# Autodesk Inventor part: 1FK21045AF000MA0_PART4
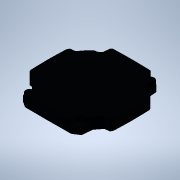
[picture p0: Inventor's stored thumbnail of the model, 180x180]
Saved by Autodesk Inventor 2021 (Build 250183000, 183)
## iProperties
Created: 2025-04
Part Number: 1FK21045AF000MA0_PART4
Material: Generic
Catalog Web Link: www.3dfindit.com
Description: -Servo synchronous motor
Document SubType Name: Modeling
Designer: psAdmin
Mass: 55.5405 g
Surface Area: 149.572 cm^2
Volume: 55.5405 cm^3
Density: 1 g/cm^3
Appearance: PSOLRGB-38-46-56
Category: PARTsolutions
Title: 1FK21045AF000MA0_PART4
Author: Cadenas PARTsolutions
Comments: Servo synchronous motor
Sending System: PARTsolutions
Preprocessor: ST-DEVELOPER v19.3
PSOL_IDENT_0: {$CADENAS_DATA/23d-libs/siemens_ag/_cat_/8b/0a/1fk21045af000ma0.prj},213 {VTYP=3D},{NB=1FK21045AF000
PSOL_IDENT_1: MA0_PART4},{LINA=1FK21045AF000MA0_PART4},{NN=1FK21045AF000MA0_PART4},{NOPRJ=TRUE},{DATE=19.08.2025 1
PSOL_IDENT_2: 4:00:48},{GEOMDATE=30.07.2025 02:00:28},{VERSION=},{LINEID=10},{WBVAR=},{WBNUMERIC=}  {NB=1FK21045AF
PSOL_IDENT_3: 000MA0_PART4},{LINA=1FK21045AF000MA0_PART4},{KT=DUMMY},{PREVIEW=../../../_pool_/a9/69/p_d211_xx_0081
PSOL_IDENT_4: 8j.png},{DESCSHORT=SIMOTICS S-1FK2 HD, SINAMICS S210 3AC 400V-480V, 2.4 Nm, 3000 rpm},{DESCLONG=SIMO
PSOL_IDENT_5: TICS S-1FK2 HD servo motor M0=2.4 Nm; PN = 0.75 kW at nN=3000 rpm (380-480 V); PN = 0.375 kW at nN=1
PSOL_IDENT_6: 500 rpm (200-240 V); degree of protection IP64; cylindrical shaft D19x40mm; absolute encoder 22-bit
PSOL_IDENT_7: + 12-bit multiturn (encoder AM22DQC); with OCC interface; plug size M17, rotatable; SIMOTICS S-1FK2
PSOL_IDENT_8: servomotorfor a wide range of uses in industrial environments. SIMOTICS S‑1FK2 servomotors are compa
PSOL_IDENT_9: ct synchronous motors with a high dynamic performance that set themselves apart as a result of their
PSOL_IDENT_10: high power density, degree of protection and overload capability. The motors are available in two v
PSOL_IDENT_11: ariants: as High Dynamic variant (highest dynamic performance as a result of the low intrinsic momen
PSOL_IDENT_12: t of inertia for applications demanding a high dynamic performance with low moved masses) - and as C
PSOL_IDENT_13: ompact variant (precise and stable closed-loop control for medium up to large moved masses as a resu
PSOL_IDENT_14: lt of a medium intrinsic moment of inertia). SIMOTICSS‑1FK2 servomotors fully exploit their strength
PSOL_IDENT_15: s in a system with the SINAMICSS210 frequency converter and simple connection using the one cable co
PSOL_IDENT_16: nnection (OCC). Advantages include the short control and positioning times, fast and precise correct
PSOL_IDENT_17: ion of disturbing quantities as well as stable control with a high dynamic performance. The servo mo
PSOL_IDENT_18: tors can be configured to address a wide range of requirements. For example with and without holding
PSOL_IDENT_19: brake, IP64 or IP65 degree of protection, singleturn or multiturn absolute encoders - to name just
PSOL_IDENT_20: a few. Further, the servomotors are available in different shaft heights extending from 20 to 100. A
PSOL_IDENT_21: shaft sealing ring is available to achieve an IP65 degree of protection and for subsequent mounting
PSOL_IDENT_22: at the motor or as spare part. SIMOTICS - the optimum motor for each and every motion control appli
PSOL_IDENT_23: cation.},{INTNO=195125050112},{SUPPLIERALTNO=1FK2104-5AF00-0MA0},{MANUID=1FK21045AF000MA0},{MANUNAME=
PSOL_IDENT_24: Siemens},{MANUTYPEDESC=Synchronous motor 1FK2-HD 2.4 NM},{AAU732=SIMOTICS},{AAO057=S-1FK2},{AAU734=S
PSOL_IDENT_25: IMOTICS S-1FK2 HD servo motor M0=2.4 Nm; PN = 0.75 kW at nN=3000 rpm (380-480 V); PN = 0.375 kW at n
PSOL_IDENT_26: N=1500 rpm (200-240 V); degree of protection IP64; cylindrical shaft D19x40mm; absolute encoder 22-b
PSOL_IDENT_27: it + 12-bit multiturn (encoder AM22DQC); with OCC interface; plug size M17, rotatable;},{AAW338=Sync
PSOL_IDENT_28: hronous motor 1FK2-HD 2.4 NM},{AAO742=SIMOTICS},{AAO663=4042948692912},{NOCUPEROU=1},{PRICEQUANTITY=
PSOL_IDENT_29: 1},{QUANTITYMIN=1},{QUANTITYINT=1},{CTN=85015100},{COO=DE},{AAO676=1FK2104-5AF00-0MA0},{AAO677=Sieme
PSOL_IDENT_30: ns AG},{ORDERUNIT=C62},{CONTENTUNIT=C62}
NB: 1FK21045AF000MA0_PART4
NT: Servo synchronous motor
NBSYN: $MANUID._PART4
LINA: 1FK21045AF000MA0_PART4
CATALOG: SIEMENS
PREVIEW: ../../../_pool_/a9/69/p_d211_xx_00818j.png
DESCSHORT: SIMOTICS S-1FK2 HD, SINAMICS S210 3AC 400V-480V, 2.4 Nm, 3000 rpm
DESCLONG: SIMOTICS S-1FK2 HD servo motor M0=2.4 Nm; PN = 0.75 kW at nN=3000 rpm (380-480 V); PN = 0.375 kW at nN=1500 rpm (200-240 V); degree of protection IP64; cylindri
INTNO: 195125050112
SUPPLIERALTNO: 1FK2104-5AF00-0MA0
MANUID: 1FK21045AF000MA0
MANUNAME: Siemens
MANUTYPEDESC: Synchronous motor 1FK2-HD 2.4 NM
AAU732: SIMOTICS
AAO057: S-1FK2
AAU734: SIMOTICS S-1FK2 HD servo motor M0=2.4 Nm; PN = 0.75 kW at nN=3000 rpm (380-480 V); PN = 0.375 kW at nN=1500 rpm (200-240 V); degree of protection IP64; cylindri
AAW338: Synchronous motor 1FK2-HD 2.4 NM
AAO742: SIMOTICS
AAO663: 4042948692912.0
NOCUPEROU: 1
PRICEQUANTITY: 1
QUANTITYMIN: 1
QUANTITYINT: 1
CTN: 85015100
COO: DE
ARTICLENO: 1FK21045AF000MA0_PART4
BOMINFO: 1FK21045AF000MA0_PART4
CREATOR: CADENAS GmbH
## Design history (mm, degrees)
feature "2025_04_17_15_40_42_0672"
body "Solid1"
